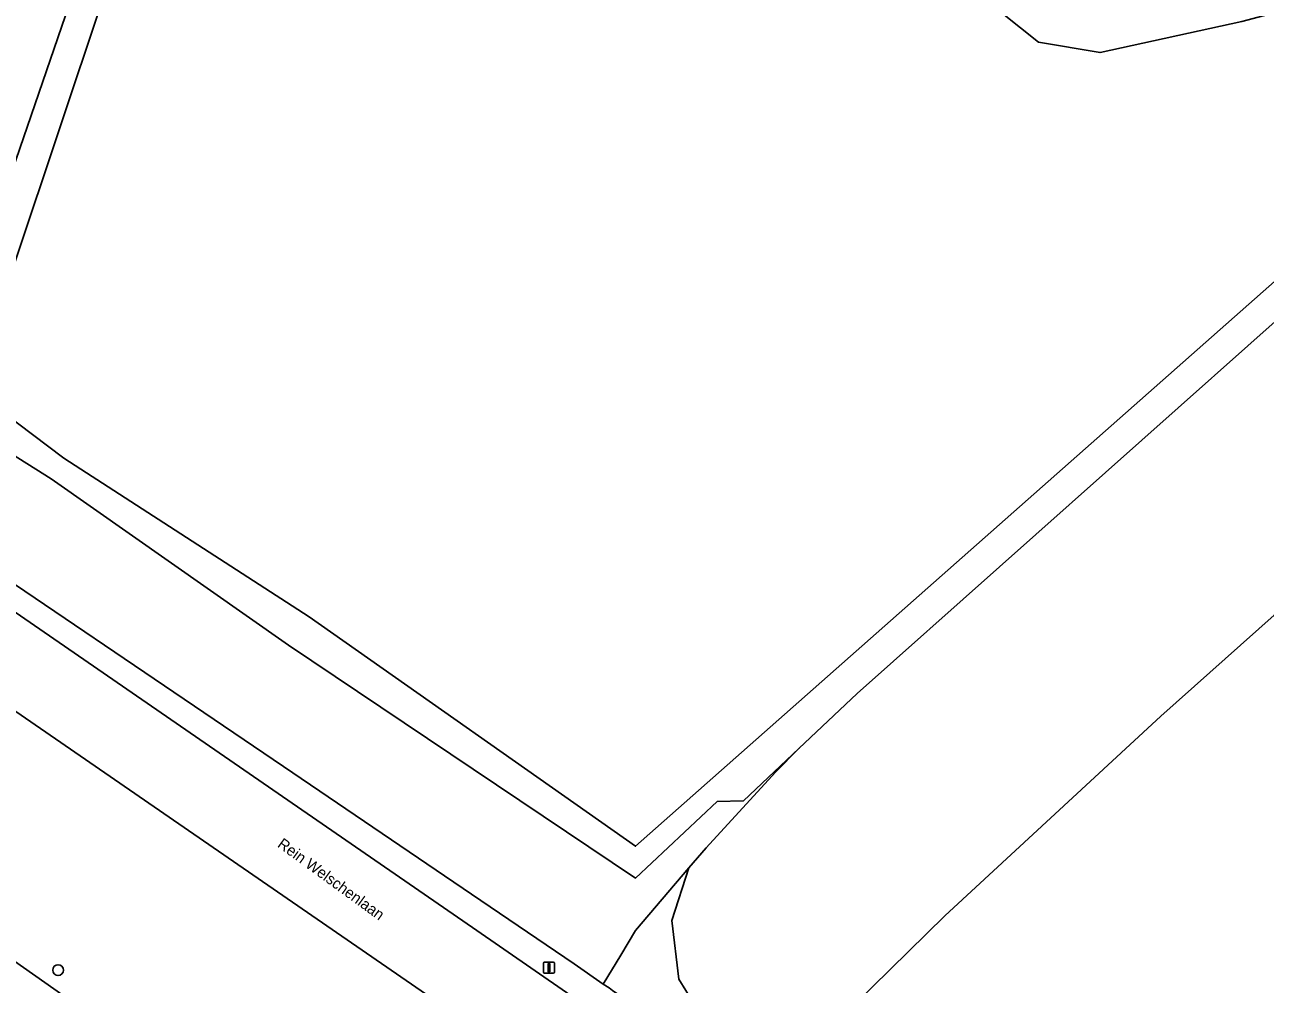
# Model space of a CAD drawing. Extents: x 155209 to 156748, y 385356 to 388487.
# Drawn here: x 156106.4 to 156219, y 386122.9 to 386210 of the extents above; entities that cross this region are included whole.
import ezdxf

# ---------------------------------------------------------------- set-up
doc = ezdxf.new("R2010")
doc.units = 0
for name, color, linetype in [('IMGEO_Boom', 7, 'Continuous'), ('IMGEO_Gemengd_bos', 7, 'Continuous'), ('IMGEO_Grasland_overig', 7, 'Continuous'), ('IMGEO_Groenvoorziening', 7, 'Continuous'), ('IMGEO_Lichtmast', 7, 'Continuous'), ('IMGEO_Loofbos', 7, 'Continuous'), ('IMGEO_Meer_plas_ven_vijver', 7, 'Continuous'), ('IMGEO_Oever', 7, 'Continuous'), ('IMGEO_Openbare_ruimte_label', 7, 'Continuous'), ('IMGEO_Rijbaan_lokaal_gesloten', 7, 'Continuous')]:
    doc.layers.add(name, color=color, linetype=linetype)

msp = doc.modelspace()

# ---------------------------------------------------------------- linework, layer by layer
at = {"layer": 'IMGEO_Boom'}
msp.add_circle((156109.39, 386124.18), 0.489, dxfattribs=at)
at = {"layer": 'IMGEO_Gemengd_bos'}
msp.add_lwpolyline([(156114.94, 386278.94), (156085.5, 386176.9), (156087.27, 386175.41), (156090.77, 386173.58), (156094.59, 386173.66), (156097.92, 386175.59), (156127, 386260.21)], dxfattribs=at)
at = {"layer": 'IMGEO_Grasland_overig'}
for points in [[(156197.31, 386305.14), (156194.77, 386298.75), (156191.06, 386287.31), (156185.02, 386274.21), (156182.97, 386266.48), (156186.73, 386259.43), (156191.91, 386249.28), (156192.16, 386232.19), (156190.79, 386220.33), (156191.99, 386216.04), (156195.15, 386211.02), (156198.41, 386208.42), (156204, 386207.47), (156216.86, 386210.3), (156228.84, 386213.49), (156231.88, 386213.32), (156237.78, 386215.24), (156247.07, 386216.12), (156244.39, 386222.35), (156226.72, 386255.93), (156207.99, 386287.92)], [(156244.82, 386145.79), (156242.86, 386154.12), (156243.46, 386156.16), (156240.46, 386170.9), (156246.65, 386177.92), (156255.64, 386186.01), (156255.25, 386187.24), (156255.17, 386187.18), (156246.86, 386180.12), (156225.61, 386161.04), (156219.81, 386156.41), (156209.51, 386147.24), (156189.89, 386129.1), (156178.33, 386117.77), (156176.68, 386116.02), (156190.74, 386108.68), (156193.35, 386109.51), (156201.55, 386107.46), (156216.55, 386112.22), (156229.06, 386128.99), (156234.77, 386136.94), (156239.69, 386143.01), (156244.7, 386144.49), (156244.23, 386145.52)]]:
    msp.add_lwpolyline(points, close=True, dxfattribs=at)
msp.add_lwpolyline([(156228.84, 386078.54), (156190.67, 386105.78), (156176.68, 386116.02), (156172.91, 386117.25), (156167.66, 386120.27), (156165.75, 386123.37), (156165.11, 386128.7), (156166.67, 386133.47), (156161.8, 386127.78), (156160.48, 386125.54), (156158.89, 386122.92), (156159.41, 386122.56), (156159.73, 386122.33), (156191.09, 386100.59), (156229.62, 386073.86)], dxfattribs=at)
at = {"layer": 'IMGEO_Groenvoorziening'}
for points in [[(156159.73, 386122.33), (156159.41, 386122.56), (156158.89, 386122.92), (156156.24, 386124.76), (156147.77, 386130.5), (156129.85, 386142.65), (156095.53, 386165.91), (156084.49, 386173.39), (156081.38, 386174.93), (156079.31, 386175.95), (156076.52, 386177.33), (156040.01, 386192.67), (156038.44, 386193.41), (156036.87, 386194.18), (156035.31, 386194.97), (156033.77, 386195.82), (156032.44, 386196.61), (156031.88, 386195.42), (156031.55, 386194.59), (156064.88, 386180.52), (156074.81, 386176.17)], [(156093, 386165.23), (156101.94, 386159.1), (156147.01, 386128.05), (156155.56, 386122.15), (156158.71, 386119.97), (156171.85, 386110.91), (156217.73, 386079.25), (156224.12, 386074.8)]]:
    msp.add_lwpolyline(points, dxfattribs=at)
msp.add_lwpolyline([(156130.32, 386153.68), (156108.77, 386168.78), (156097.92, 386175.59), (156094.59, 386173.66), (156090.77, 386173.58), (156087.27, 386175.41), (156085.5, 386176.9), (156084.49, 386173.39), (156095.53, 386165.91), (156129.85, 386142.65), (156147.77, 386130.5), (156156.24, 386124.76), (156158.89, 386122.92), (156160.48, 386125.54), (156161.8, 386127.78), (156166.67, 386133.47), (156168.23, 386135.29), (156174.54, 386142.16), (156176.65, 386144.29), (156171.62, 386139.54), (156169.23, 386139.5), (156161.8, 386132.54)], close=True, dxfattribs=at)
at = {"layer": 'IMGEO_Lichtmast'}
for p, q in [((156153.46, 386124), (156153.46, 386124.8)), ((156153.46, 386124.8), (156153.46, 386124)), ((156153.56, 386124.9), (156154.35, 386124.9)), ((156154.35, 386124.9), (156153.56, 386124.9)), ((156154.45, 386124.8), (156154.45, 386124)), ((156154.45, 386124), (156154.45, 386124.8)), ((156154.35, 386123.9), (156153.56, 386123.9)), ((156153.56, 386123.9), (156154.35, 386123.9))]:
    msp.add_line(p, q, dxfattribs=at)
msp.add_lwpolyline([(156153.88, 386124.78), (156154.03, 386124.78), (156154.03, 386124.03), (156153.88, 386124.03), (156153.88, 386124.78)], dxfattribs=at)
for centre, start, end in [((156153.56, 386124.8), 90, 180), ((156153.56, 386124.8), 90, 180), ((156154.35, 386124.8), 0, 90), ((156154.35, 386124.8), 360, 90), ((156153.56, 386124), 180, 270), ((156153.56, 386124), 180, 270), ((156154.35, 386124), 270, 0), ((156154.35, 386124), 270, 0)]:
    msp.add_arc(centre, 0.1, start, end, dxfattribs=at)
at = {"layer": 'IMGEO_Loofbos'}
msp.add_lwpolyline([(156220.7, 386183.8), (156181.94, 386149.28), (156176.65, 386144.29), (156174.54, 386142.16), (156168.23, 386135.29), (156166.67, 386133.47), (156165.11, 386128.7), (156165.75, 386123.37), (156167.66, 386120.27), (156172.91, 386117.25), (156176.68, 386116.02), (156178.33, 386117.77), (156189.89, 386129.1), (156209.51, 386147.24), (156219.81, 386156.41)], dxfattribs=at)
msp.add_lwpolyline([(156086.24, 386160.94), (156083.54, 386162.84), (156082.84, 386161.53), (156081.65, 386159.3), (156074.85, 386146.49), (156076.42, 386145.39), (156078.08, 386144.22), (156148.48, 386094.74), (156151.39, 386092.68), (156153.85, 386090.94), (156156.71, 386094.13), (156162.57, 386100.65), (156166.86, 386105.42), (156156.69, 386112.43), (156153.6, 386114.56), (156143.24, 386121.7)], close=True, dxfattribs=at)
at = {"layer": 'IMGEO_Meer_plas_ven_vijver'}
for points in [[(156129.19, 386259.44), (156101.58, 386176.93), (156109.91, 386170.67), (156132.18, 386156.24), (156161.82, 386135.42), (156223.23, 386189.68), (156224.56, 386190.89), (156225.68, 386191.41), (156225.25, 386192.45), (156227.39, 386193.5), (156228.36, 386193.93), (156228.11, 386194.93), (156248.12, 386212.14)], [(156216.86, 386210.3), (156204, 386207.47), (156198.41, 386208.42), (156195.15, 386211.02)]]:
    msp.add_lwpolyline(points, dxfattribs=at)
at = {"layer": 'IMGEO_Oever'}
for points in [[(156127, 386260.21), (156097.92, 386175.59), (156108.77, 386168.78), (156130.32, 386153.68), (156161.8, 386132.54), (156169.23, 386139.5), (156171.62, 386139.54), (156176.65, 386144.29), (156181.94, 386149.28), (156220.7, 386183.8), (156222.7, 386185.75), (156230.23, 386193.11), (156248.68, 386209.64), (156250.28, 386211.79)], [(156248.12, 386212.14), (156228.11, 386194.93), (156228.36, 386193.93), (156227.39, 386193.5), (156225.25, 386192.45), (156225.68, 386191.41), (156224.56, 386190.89), (156223.23, 386189.68), (156161.82, 386135.42), (156132.18, 386156.24), (156109.91, 386170.67), (156101.58, 386176.93), (156129.19, 386259.44)]]:
    msp.add_lwpolyline(points, dxfattribs=at)
at = {"layer": 'IMGEO_Rijbaan_lokaal_gesloten'}
for points in [[(156079.42, 386165.49), (156083.54, 386162.84), (156086.24, 386160.94), (156143.24, 386121.7), (156153.6, 386114.56), (156156.69, 386112.43), (156166.86, 386105.42), (156212.41, 386074.03), (156213.35, 386073.3)], [(156224.12, 386074.8), (156217.73, 386079.25), (156171.85, 386110.91), (156158.71, 386119.97), (156155.56, 386122.15), (156147.01, 386128.05), (156101.94, 386159.1), (156093, 386165.23)], [(156097.82, 386126.26), (156125.95, 386106.41), (156135.52, 386099.82), (156174.48, 386072.45), (156203.46, 386051.76), (156209.24, 386046.84), (156212.06, 386049.11), (156212.18, 386049.2), (156205.14, 386054.59), (156153.85, 386090.94), (156151.39, 386092.68), (156148.48, 386094.74), (156078.08, 386144.22)]]:
    msp.add_lwpolyline(points, dxfattribs=at)

# ---------------------------------------------------------------- texts
at = {"layer": 'IMGEO_Openbare_ruimte_label'}
msp.add_text('Rein Welschenlaan', height=1, rotation=323.9895, dxfattribs=at).set_placement((156129.23, 386135.43))

doc.saveas('drawing.dxf')
